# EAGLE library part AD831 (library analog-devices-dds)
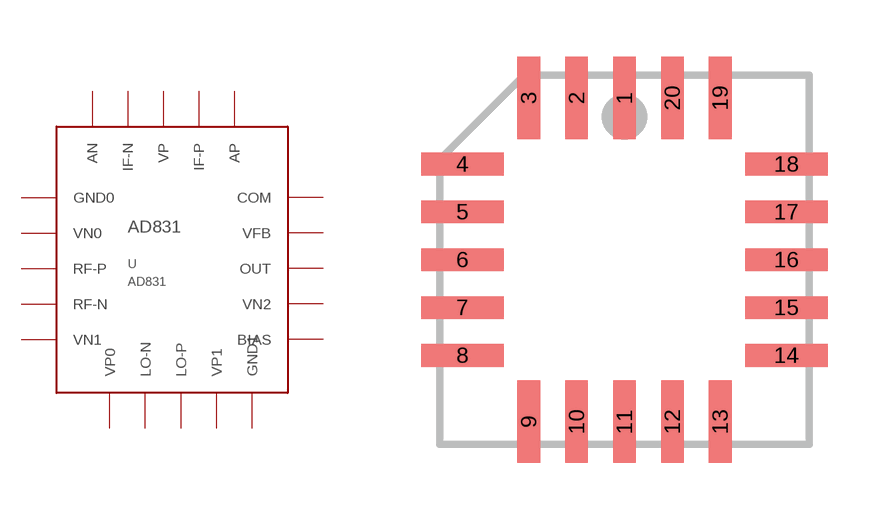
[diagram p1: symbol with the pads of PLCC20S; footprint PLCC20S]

Designator prefix -

## AD831  [PLCC20S]
1  VP
2  IF-N
3  AN
4  GND0
5  VN0
6  RF-P
7  RF-N
8  VN1
9  VP0
10  LO-N
11  LO-P
12  VP1
13  GND1
14  BIAS
15  VN2
16  OUT
17  VFB
18  COM
19  AP
20  IF-P

## Footprint PLCC20S (pad centres in mm)
PLASTIC LEADED CHIP CARRIER square, package type L
smd 0.6 x 2.2: 1 0,4.3; 2 -1.27,4.3; 3 -2.54,4.3; 9 -2.54,-4.3; 10 -1.27,-4.3; 11 0,-4.3; 12 1.27,-4.3; 13 2.54,-4.3; 19 2.54,4.3; 20 1.27,4.3
smd 2.2 x 0.6: 4 -4.3,2.54; 5 -4.3,1.27; 6 -4.3,0; 7 -4.3,-1.27; 8 -4.3,-2.54; 14 4.3,-2.54; 15 4.3,-1.27; 16 4.3,0; 17 4.3,1.27; 18 4.3,2.54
